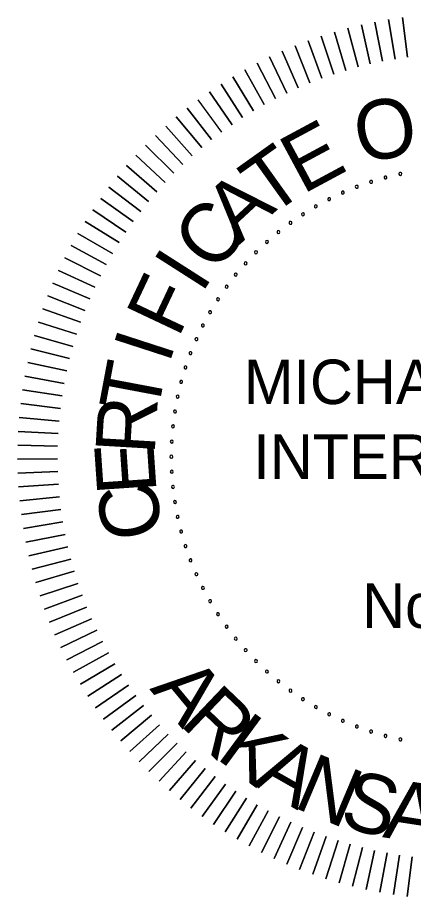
# Model space of a CAD drawing. Extents: x 155 to 3386, y 68 to 2138.
# Drawn here: x 2702.4 to 2813.7, y 323.6 to 570.5 of the extents above; entities that cross this region are included whole.
import ezdxf

# ---------------------------------------------------------------- set-up
doc = ezdxf.new("R2010")
doc.units = 0
doc.layers.add('G-ANNO-TEXT', color=7, linetype='Continuous')

msp = doc.modelspace()

# ---------------------------------------------------------------- linework, layer by layer
at = {"layer": 'G-ANNO-TEXT'}
for points in [[(2812.05, 559.35), (2810.58, 570.48)], [(2810.58, 570.48), (2812.05, 559.35)], [(2801.55, 557.46), (2799.04, 568.4)], [(2799.04, 568.4), (2801.55, 557.46)], [(2805.03, 558.2), (2802.86, 569.21)], [(2802.86, 569.21), (2805.03, 558.2)], [(2808.53, 558.83), (2806.71, 569.91)], [(2806.71, 569.91), (2808.53, 558.83)], [(2794.67, 555.65), (2791.48, 566.41)], [(2791.48, 566.41), (2794.67, 555.65)], [(2798.1, 556.61), (2795.24, 567.46)], [(2795.24, 567.46), (2798.1, 556.61)], [(2787.92, 553.42), (2784.06, 563.95)], [(2784.06, 563.95), (2787.92, 553.42)], [(2791.28, 554.59), (2787.75, 565.24)], [(2787.75, 565.24), (2791.28, 554.59)], [(2781.32, 550.76), (2776.81, 561.04)], [(2776.81, 561.04), (2781.32, 550.76)], [(2784.6, 552.14), (2780.41, 562.55)], [(2780.41, 562.55), (2784.6, 552.14)], [(2778.09, 549.28), (2773.25, 559.41)], [(2773.25, 559.41), (2778.09, 549.28)], [(2771.77, 546.02), (2766.31, 555.82)], [(2766.31, 555.82), (2771.77, 546.02)], [(2774.9, 547.7), (2769.75, 557.67)], [(2769.75, 557.67), (2774.9, 547.7)], [(2768.69, 544.24), (2762.92, 553.86)], [(2762.92, 553.86), (2768.69, 544.24)], [(2765.66, 542.36), (2759.6, 551.8)], [(2759.6, 551.8), (2765.66, 542.36)], [(2762.7, 540.39), (2756.34, 549.64)], [(2756.34, 549.64), (2762.7, 540.39)], [(2759.8, 538.33), (2753.16, 547.37)], [(2756.97, 536.18), (2750.04, 545.01)], [(2750.04, 545.01), (2756.97, 536.18)], [(2754.21, 533.94), (2747.01, 542.55)], [(2747.01, 542.55), (2754.21, 533.94)], [(2751.52, 531.62), (2744.05, 539.99)], [(2744.05, 539.99), (2751.52, 531.62)], [(2748.9, 529.21), (2741.17, 537.34)], [(2741.17, 537.34), (2748.9, 529.21)], [(2746.36, 526.72), (2738.38, 534.61)], [(2738.38, 534.61), (2746.36, 526.72)], [(2743.9, 524.15), (2735.68, 531.79)], [(2735.68, 531.79), (2743.9, 524.15)], [(2741.52, 521.51), (2733.06, 528.88)], [(2733.06, 528.88), (2741.52, 521.51)], [(2739.23, 518.79), (2730.54, 525.89)], [(2730.54, 525.89), (2739.23, 518.79)], [(2737.02, 516), (2728.11, 522.83)], [(2728.11, 522.83), (2737.02, 516)], [(2734.9, 513.14), (2725.78, 519.69)], [(2725.78, 519.69), (2734.9, 513.14)], [(2732.87, 510.22), (2723.55, 516.48)], [(2723.55, 516.48), (2732.87, 510.22)], [(2730.93, 507.24), (2721.42, 513.2)], [(2721.42, 513.2), (2730.93, 507.24)], [(2729.09, 504.2), (2719.4, 509.86)], [(2719.4, 509.86), (2729.09, 504.2)], [(2727.35, 501.1), (2717.48, 506.45)], [(2717.48, 506.45), (2727.35, 501.1)], [(2725.7, 497.94), (2715.67, 502.98)], [(2715.67, 502.98), (2725.7, 497.94)], [(2724.15, 494.74), (2713.97, 499.46)], [(2713.97, 499.46), (2724.15, 494.74)], [(2722.71, 491.49), (2712.38, 495.89)], [(2712.38, 495.89), (2722.71, 491.49)], [(2721.36, 488.2), (2710.91, 492.27)], [(2710.91, 492.27), (2721.36, 488.2)], [(2720.12, 484.86), (2709.54, 488.61)], [(2709.54, 488.61), (2720.12, 484.86)], [(2718.99, 481.49), (2708.3, 484.9)], [(2708.3, 484.9), (2718.99, 481.49)], [(2717.96, 478.09), (2707.17, 481.16)], [(2707.17, 481.16), (2717.96, 478.09)], [(2717.05, 474.65), (2706.16, 477.38)], [(2706.16, 477.38), (2717.05, 474.65)], [(2716.23, 471.19), (2705.27, 473.58)], [(2705.27, 473.58), (2716.23, 471.19)], [(2715.53, 467.7), (2704.5, 469.74)], [(2704.5, 469.74), (2715.53, 467.7)], [(2714.94, 464.2), (2703.85, 465.89)], [(2703.85, 465.89), (2714.94, 464.2)], [(2714.46, 460.67), (2703.32, 462.02)], [(2703.32, 462.02), (2714.46, 460.67)], [(2714.09, 457.13), (2702.91, 458.13)], [(2702.91, 458.13), (2714.09, 457.13)], [(2713.83, 453.59), (2702.63, 454.23)], [(2702.63, 454.23), (2713.83, 453.59)], [(2713.68, 450.03), (2702.46, 450.32)], [(2702.46, 450.32), (2713.68, 450.03)], [(2713.65, 446.48), (2702.42, 446.41)], [(2702.42, 446.41), (2713.65, 446.48)], [(2713.72, 442.92), (2702.51, 442.51)], [(2702.51, 442.51), (2713.72, 442.92)], [(2713.91, 439.37), (2702.71, 438.6)], [(2702.71, 438.6), (2713.91, 439.37)], [(2714.21, 435.82), (2703.04, 434.71)], [(2703.04, 434.71), (2714.21, 435.82)], [(2714.62, 432.29), (2703.49, 430.82)], [(2703.49, 430.82), (2714.62, 432.29)], [(2715.14, 428.77), (2704.06, 426.96)], [(2704.06, 426.96), (2715.14, 428.77)], [(2715.77, 425.27), (2704.76, 423.11)], [(2704.76, 423.11), (2715.77, 425.27)], [(2716.51, 421.79), (2705.57, 419.28)], [(2705.57, 419.28), (2716.51, 421.79)], [(2717.36, 418.34), (2706.51, 415.49)], [(2706.51, 415.49), (2717.36, 418.34)], [(2718.32, 414.91), (2707.56, 411.72)], [(2707.56, 411.72), (2718.32, 414.91)], [(2719.38, 411.52), (2708.73, 407.99)], [(2708.73, 407.99), (2719.38, 411.52)], [(2720.55, 408.16), (2710.01, 404.3)], [(2710.01, 404.3), (2720.55, 408.16)], [(2721.83, 404.84), (2711.42, 400.65)], [(2711.42, 400.65), (2721.83, 404.84)], [(2723.21, 401.56), (2712.93, 397.05)], [(2712.93, 397.05), (2723.21, 401.56)], [(2724.69, 398.33), (2714.56, 393.5)], [(2714.56, 393.5), (2724.69, 398.33)], [(2726.27, 395.15), (2716.3, 390)], [(2716.3, 390), (2726.27, 395.15)], [(2727.95, 392.01), (2718.15, 386.55)], [(2718.15, 386.55), (2727.95, 392.01)], [(2729.73, 388.93), (2720.11, 383.17)], [(2720.11, 383.17), (2729.73, 388.93)], [(2731.61, 385.91), (2722.17, 379.84)], [(2722.17, 379.84), (2731.61, 385.91)], [(2733.58, 382.95), (2724.33, 376.59)], [(2724.33, 376.59), (2733.58, 382.95)], [(2735.64, 380.05), (2726.6, 373.4)], [(2726.6, 373.4), (2735.64, 380.05)], [(2737.79, 377.22), (2728.96, 370.29)], [(2728.96, 370.29), (2737.79, 377.22)], [(2740.03, 374.45), (2731.42, 367.25)], [(2731.42, 367.25), (2740.03, 374.45)], [(2742.35, 371.76), (2733.98, 364.29)], [(2733.98, 364.29), (2742.35, 371.76)], [(2744.76, 369.14), (2736.62, 361.42)], [(2736.62, 361.42), (2744.76, 369.14)], [(2747.25, 366.6), (2739.36, 358.62)], [(2739.36, 358.62), (2747.25, 366.6)], [(2749.82, 364.14), (2742.18, 355.92)], [(2742.18, 355.92), (2749.82, 364.14)], [(2745.09, 353.31), (2752.46, 361.76)], [(2752.46, 361.76), (2745.09, 353.31)], [(2748.08, 350.78), (2755.18, 359.47)], [(2755.18, 359.47), (2748.08, 350.78)], [(2751.14, 348.36), (2757.97, 357.26)], [(2757.97, 357.26), (2751.14, 348.36)], [(2754.28, 346.03), (2760.83, 355.14)], [(2760.83, 355.14), (2754.28, 346.03)], [(2757.49, 343.8), (2763.75, 353.11)], [(2763.75, 353.11), (2757.49, 343.8)], [(2760.77, 341.67), (2766.73, 351.18)], [(2766.73, 351.18), (2760.77, 341.67)], [(2764.11, 339.64), (2769.77, 349.34)], [(2769.77, 349.34), (2764.11, 339.64)], [(2767.52, 337.73), (2772.87, 347.59)], [(2772.87, 347.59), (2767.52, 337.73)], [(2770.99, 335.92), (2776.03, 345.94)], [(2776.03, 345.94), (2770.99, 335.92)], [(2774.51, 334.22), (2779.23, 344.4)], [(2779.23, 344.4), (2774.51, 334.22)], [(2778.08, 332.63), (2782.48, 342.95)], [(2782.48, 342.95), (2778.08, 332.63)], [(2781.7, 331.15), (2785.77, 341.61)], [(2785.77, 341.61), (2781.7, 331.15)], [(2785.36, 329.79), (2789.11, 340.37)], [(2789.11, 340.37), (2785.36, 329.79)], [(2789.07, 328.54), (2792.48, 339.24)], [(2792.48, 339.24), (2789.07, 328.54)], [(2792.81, 327.42), (2795.88, 338.21)], [(2795.88, 338.21), (2792.81, 327.42)], [(2796.59, 326.4), (2799.32, 337.29)], [(2799.32, 337.29), (2796.59, 326.4)], [(2800.39, 325.51), (2802.78, 336.48)], [(2802.78, 336.48), (2800.39, 325.51)], [(2804.23, 324.74), (2806.27, 335.78)], [(2806.27, 335.78), (2804.23, 324.74)], [(2808.08, 324.09), (2809.77, 335.19)], [(2809.77, 335.19), (2808.08, 324.09)], [(2811.95, 323.56), (2813.3, 334.7)], [(2813.3, 334.7), (2811.95, 323.56)]]:
    msp.add_lwpolyline(points, dxfattribs=at)
for centre, start, end in [((2805.84, 525.55), 15, 195), ((2809.98, 526.55), 12, 192), ((2809.98, 526.55), 192, 12), ((2801.77, 524.35), 18, 198), ((2801.77, 524.35), 198, 18), ((2805.84, 525.55), 195, 15), ((2793.83, 521.3), 24, 204), ((2793.83, 521.3), 204, 24), ((2797.76, 522.93), 21, 201), ((2797.76, 522.93), 201, 21), ((2789.99, 519.47), 27, 207), ((2789.99, 519.47), 207, 27), ((2786.25, 517.44), 30, 210), ((2786.25, 517.44), 210, 30), ((2782.63, 515.22), 33, 213), ((2782.63, 515.22), 213, 33), ((2779.13, 512.81), 36, 216), ((2779.13, 512.81), 216, 36), ((2775.75, 510.22), 39, 219), ((2775.75, 510.22), 219, 39), ((2772.52, 507.46), 42, 222), ((2772.52, 507.46), 222, 42), ((2769.43, 504.53), 45, 225), ((2769.43, 504.53), 225, 45), ((2766.51, 501.45), 48, 228), ((2766.51, 501.45), 228, 48), ((2763.75, 498.22), 51, 231), ((2763.75, 498.22), 231, 51), ((2761.16, 494.84), 54, 234), ((2761.16, 494.84), 234, 54), ((2758.75, 491.34), 57, 237), ((2758.75, 491.34), 237, 57), ((2756.53, 487.71), 60, 240), ((2756.53, 487.71), 240, 60), ((2754.5, 483.98), 63, 243), ((2754.5, 483.98), 243, 63), ((2752.67, 480.14), 66, 246), ((2752.67, 480.14), 246, 66), ((2751.04, 476.21), 69, 249), ((2751.04, 476.21), 249, 69), ((2749.62, 472.2), 72, 252), ((2749.62, 472.2), 252, 72), ((2748.41, 468.13), 75, 255), ((2748.41, 468.13), 255, 75), ((2747.42, 463.99), 78, 258), ((2747.42, 463.99), 258, 78), ((2746.65, 459.81), 81, 261), ((2746.65, 459.81), 261, 81), ((2746.09, 455.6), 84, 264), ((2746.09, 455.6), 264, 84), ((2745.76, 451.36), 87, 267), ((2745.76, 451.36), 267, 87), ((2745.65, 447.11), 90, 270), ((2745.65, 447.11), 270, 90), ((2745.76, 442.86), 93, 273), ((2745.76, 442.86), 273, 93), ((2746.09, 438.62), 96, 276), ((2746.09, 438.62), 276, 96), ((2746.65, 434.4), 99, 279), ((2746.65, 434.4), 279, 99), ((2747.42, 430.22), 102, 282), ((2747.42, 430.22), 282, 102), ((2748.41, 426.09), 105, 285), ((2748.41, 426.09), 285, 105), ((2749.62, 422.01), 108, 288), ((2749.62, 422.01), 288, 108), ((2751.04, 418), 111, 291), ((2751.04, 418), 291, 111), ((2752.67, 414.07), 114, 294), ((2752.67, 414.07), 294, 114), ((2754.5, 410.24), 117, 297), ((2754.5, 410.24), 297, 117), ((2756.53, 406.5), 120, 300), ((2756.53, 406.5), 300, 120), ((2758.75, 402.87), 123, 303), ((2758.75, 402.87), 303, 123), ((2761.16, 399.37), 126, 306), ((2761.16, 399.37), 306, 126), ((2763.75, 396), 129, 309), ((2763.75, 396), 309, 129), ((2766.51, 392.76), 132, 312), ((2766.51, 392.76), 312, 132), ((2769.43, 389.68), 135, 315), ((2769.43, 389.68), 315, 135), ((2772.52, 386.75), 138, 318), ((2772.52, 386.75), 318, 138), ((2775.75, 383.99), 141, 321), ((2775.75, 383.99), 321, 141), ((2779.13, 381.4), 144, 324), ((2779.13, 381.4), 324, 144), ((2782.63, 378.99), 147, 327), ((2782.63, 378.99), 327, 147), ((2786.25, 376.77), 150, 330), ((2786.25, 376.77), 330, 150), ((2789.99, 374.74), 153, 333), ((2789.99, 374.74), 333, 153), ((2793.83, 372.91), 156, 336), ((2793.83, 372.91), 336, 156), ((2797.76, 371.29), 159, 339), ((2797.76, 371.29), 339, 159), ((2801.77, 369.87), 162, 342), ((2801.77, 369.87), 342, 162), ((2805.84, 368.66), 165, 345), ((2805.84, 368.66), 345, 165), ((2809.98, 367.67), 348, 168), ((2809.98, 367.67), 168, 348)]:
    msp.add_arc(centre, 0.417, start, end, dxfattribs=at)

# ---------------------------------------------------------------- texts
for s, rotation, p in [('O', 10.7295, (2798.7, 529.43)), ('E', 28.279, (2782.52, 520.7)), ('T', 35.5725, (2773.22, 514.25)), ('A', 42.8659, (2764.75, 506.55)), ('C', 50.1594, (2757.74, 498.22)), ('I', 57.4529, (2754.12, 492.64)), ('F', 64.7464, (2747.58, 480.18)), ('I', 72.0398, (2744.99, 472.85)), ('T', 79.3333, (2741.68, 458.49)), ('R', 86.6268, (2740.92, 447.48)), ('E', 93.9203, (2741.53, 437.06)), ('C', 101.2137, (2743.66, 425.47)), ('A', 309.5859, (2739.4, 381.84)), ('R', 316.3356, (2747.67, 372.01)), ('K', 323.6428, (2757.87, 362.55)), ('A', 330.3925, (2768.28, 355.03)), ('N', 337.1422, (2779.51, 348.78)), ('S', 344.4494, (2792.4, 343.56)), ('A', 351.1991, (2804.81, 340.23))]:
    msp.add_text(s, height=16.67, rotation=rotation, dxfattribs=at).set_placement(p)
for s, height, p in [('MICHAEL BAKER', 12.5016, (2766.03, 461.88)), (' INTERNATIONAL', 12.5016, (2764.02, 440.86)), (' No. 1126', 12.502, (2794.6, 399))]:
    msp.add_text(s, height=height, dxfattribs=at).set_placement(p)

doc.saveas('drawing.dxf')
